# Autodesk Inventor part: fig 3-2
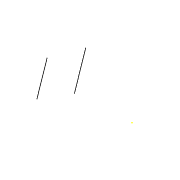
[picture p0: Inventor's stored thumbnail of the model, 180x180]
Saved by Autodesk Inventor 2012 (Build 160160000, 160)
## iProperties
Created: 2011-07
Part Number: fig 3-2
Material: Default
Document SubType Name: Modeling
Designer: CadCim
Density: 1 g/cm^3
Author: CadCim
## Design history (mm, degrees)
sketch "Sketch1"
  geometry: L1 (-29, 4)-(-20, -8); L2 (-16, -0.965)-(-25.943, 12.292); 1 further point
  constraints: 4 end point, 1 parallel, 1 other
